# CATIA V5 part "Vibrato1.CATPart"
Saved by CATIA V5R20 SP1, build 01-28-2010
Part number: Vibrato1
Bounding box of the stored display mesh (mm): x -45 to 45, y -32 to 1, z 25 to 40
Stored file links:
  F:\Pro\Emplois\1_Chercheur\ThinkMOTION\MMS\MMS_GR1\abruchon\Catia\Vibrato1.CATPart
  F:\Pro\Emplois\1_Chercheur\ThinkMOTION\MMS\MMS_GR1\abruchon\Catia\Vibrato.CATProduct
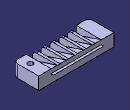
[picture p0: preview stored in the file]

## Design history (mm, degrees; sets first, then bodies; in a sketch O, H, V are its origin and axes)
Set1
  Plane1 to Plane6: linked copy from another document
Body1 (main body)
  Sketch1 on Plane1, origin (0, 0, 0), H (1, 0, 0), V (0, 1, 0)
    line L1 (-45, -2) -> (45, -2)
    line L2 (45, -2) -> (45, -32)
    line L3 (45, -32) -> (-45, -32)
    line L4 (-45, -32) -> (-45, -2)
    reference intersected line E1 through (0, -2) direction (-1, 0) from Plane2
    reference intersected line E2 through (-45, 0) direction (0, 1) from Plane3
    reference intersected line E3 through (45, 0) direction (0, 1) from Plane4
    reference intersected line E4 through (0, -32) direction (-1, 0) from Plane5
    distance L1 E1 = 0
    distance L4 E2 = 0
    distance L2 E3 = 0
    distance L3 E4 = 0
    horizontal: L1 H, L3 H
    vertical: L2 V, L4 V
  Pad1: profile Sketch1, direction (0, 0, 1), up to Plane6
  Sketch2 on face of Pad1 from Sketch1.L2, origin (45, 0, 0), H (0, 1, 0), V (0, 0, 1)
    line L1 (-40, 25) -> (10, 25)
    line L2 (10, 25) -> (10, -15)
    line L3 (10, -15) -> (-40, -15)
    line L4 (-40, -15) -> (-40, 25)
    reference projected line E1 (-32, 40) -> (-2, 40) from edge [face of Pad1 from Sketch1.L2 | end face of Pad1]
    distance E1 L1 = 15
    horizontal: L1 H, L3 H
    vertical: L2 V, L4 V
  Pocket1: profile Sketch2, direction (-1, 0, 0), through (limit type 6)
  Sketch3 on face of Pad1 from Sketch1.L2, origin (45, 0, 0), H (0, 1, 0), V (0, 0, 1)
    line L1 (-9, 35) -> (1, 35)
    point P2 (1, 35)
    line L2 (1, 35) -> (-9, 34)
    line L3 (-9, 34) -> (-9, 35)
    reference projected line E1 (-2, 0) -> (-2, 40) from edge [face of Pad1 from Sketch1.L1 | face of Pad1 from Sketch1.L2]
    reference projected line E2 (-32, 40) -> (-2, 40) from edge [face of Pad1 from Sketch1.L2 | end face of Pad1]
    distance P2 E1 = 3
    distance L1 E2 = 5
    length L3 = 1
    horizontal: L1 H
    vertical: L3 V
  Pad2: profile Sketch3, direction (-1, 0, 0), up to face of Pad1 from Sketch1.L4
  Sketch4 on face of Pad1 from Sketch1.L1, origin (0, -2, 0), H (-1, 0, 0), V (0, 0, 1)
    line L1 (-30, 40) -> (-45, 40)
    line L2 (-45, 40) -> (-45, 25)
    line L3 (-45, 25) -> (-30, 25)
    line L4 (-30, 25) -> (-30, 40)
    reference projected line E1 (-45, 25) -> (45, 25) from edge [face of Pocket1 from Sketch2.L1 | face of Pad1 from Sketch1.L1]
    reference projected line E2 (45, 40) -> (-45, 40) from edge [end face of Pad1 | face of Pad1 from Sketch1.L1]
    reference projected line E3 (-45, 0) -> (-45, 40) from edge [face of Pad1 from Sketch1.L1 | face of Pad1]
    line L5 (30, 40) -> (45, 40)
    line L6 (45, 40) -> (45, 25)
    line L7 (45, 25) -> (30, 25)
    line L8 (30, 25) -> (30, 40)
    reference projected line E4 (45, 0) -> (45, 40) from edge [face of Pad1 | face of Pad1 from Sketch1.L1]
    reference projected line E5 (45, 40) -> (-45, 40) from edge [end face of Pad1 | face of Pad1 from Sketch1.L1]
    reference projected line E6 (-45, 25) -> (45, 25) from edge [face of Pocket1 from Sketch2.L1 | face of Pad1 from Sketch1.L1]
    distance L3 E1 = 0
    distance L1 E2 = 0
    distance E3 L2 = 0
    distance L6 E4 = 0
    distance L5 E5 = 0
    distance L7 E6 = 0
    horizontal: L1 H, L3 H, L5 H, L7 H
    vertical: L2 V, L4 V, L6 V, L8 V
  Pocket2: profile Sketch4, direction (0, 1, 0), through (limit type 6)
  Sketch5 on face of Pad1, origin (45, 0, 0), H (0, 1, 0), V (0, 0, 1)
    line L1 (-32, 40) -> (-32, 40)
    reference projected line E1 (-32, 40) -> (-2, 40) from edge [face of Pad1 from Sketch1.L2 | end face of Pad1]
    line L2 (-32, 30) -> (-2, 40)
    point P3 (-32, 30)
    point P4 (-2, 40)
    line L3 (-2, 40) -> (-32, 40)
    line L4 (-32, 40) -> (-32, 30)
    reference projected line E2 (-32, 40) -> (-2, 40) from edge [face of Pad1 from Sketch1.L2 | end face of Pad1]
    reference projected line E3 (-2, 0) -> (-2, 40) from edge [face of Pocket2 | face of Pad1]
    reference projected line E4 (-32, 0) -> (-32, 40) from edge [face of Pad1 | face of Pad1 from Sketch1.L3]
    reference projected line E5 (-2, 25) -> (-32, 25) from edge [face of Pad1 from Sketch1.L2 | face of Pocket1 from Sketch2.L1]
    distance L1 E1 = 0
    distance L3 E2 = 0
    distance E3 P4 = 0
    distance L4 E4 = 0
    distance P3 E5 = 5
    horizontal: L1 H, L3 H
    vertical: L4 V
  Pocket3: profile Sketch5, direction (-1, 0, 0), through (limit type 6)
  Sketch6 on face of Pad1 from Sketch1.L3, origin (0, -32, 0), H (1, 0, 0), V (0, 0, 1)
    line L1 (30, 40) -> (45, 40)
    line L2 (45, 40) -> (45, 25)
    line L3 (45, 25) -> (30, 25)
    line L4 (30, 25) -> (30, 40)
    reference intersected line E1 through (45, 0) direction (0, 1) from Plane4
    reference projected line E2 (45, 25) -> (-45, 25) from edge [face of Pad1 from Sketch1.L3 | face of Pocket1 from Sketch2.L1]
    reference projected line E3 (45, 40) -> (-45, 40) from edge [face of Pocket2 | face of Pocket3 from Sketch5.L2]
    line L5 (-45, 40) -> (-30, 40)
    line L6 (-30, 40) -> (-30, 25)
    line L7 (-30, 25) -> (-45, 25)
    line L8 (-45, 25) -> (-45, 40)
    reference projected line E4 (45, 40) -> (-45, 40) from edge [face of Pocket2 | face of Pocket3 from Sketch5.L2]
    reference projected line E5 (-45, 40) -> (-45, 30) from edge [face of Pad1 | face of Pocket3 from Sketch5.L2]
    reference projected line E6 (45, 25) -> (-45, 25) from edge [face of Pad1 from Sketch1.L3 | face of Pocket1 from Sketch2.L1]
    line L9 (-22.5, 25) -> (-22.5, 40)
    line L10 (-22.5, 40) -> (-19.5, 40)
    line L11 (-19.5, 40) -> (-19.5, 25)
    point P12 (-19.5, 25)
    line L12 (-19.5, 25) -> (-22.5, 25)
    line L13 (-12, 40) -> (-9, 40)
    line L14 (-9, 40) -> (-9, 25)
    line L15 (-9, 25) -> (-12, 25)
    line L16 (-12, 25) -> (-12, 40)
    line L17 (-1.5, 40) -> (1.5, 40)
    line L18 (1.5, 40) -> (1.5, 25)
    line L19 (1.5, 25) -> (-1.5, 25)
    line L20 (-1.5, 25) -> (-1.5, 40)
    line L21 (9, 40) -> (12, 40)
    line L22 (12, 40) -> (12, 25)
    line L23 (12, 25) -> (9, 25)
    line L24 (9, 25) -> (9, 40)
    line L25 (19.5, 40) -> (22.5, 40)
    line L26 (22.5, 40) -> (22.5, 25)
    line L27 (22.5, 25) -> (19.5, 25)
    line L28 (19.5, 25) -> (19.5, 40)
    distance E1 L2 = 0
    distance L3 E2 = 0
    distance L1 E3 = 0
    distance L5 E4 = 0
    distance L8 E5 = 0
    distance E6 L7 = 0
    length L5 = 15
    distance L9 L6 = 7.5
    length L10 = 3
    length L13 = 3
    distance L16 L6 = 18 (reference)
    length L17 = 3
    distance L20 L6 = 28.5 (reference)
    length L21 = 3
    distance L24 L6 = 39 (reference)
    length L25 = 3
    distance L28 L6 = 49.5 (reference)
    distance L16 L11 = 7.5
    distance L14 L20 = 7.5
    distance L18 L24 = 7.5
    distance L22 L28 = 7.5
    horizontal: L1 H, L3 H, L5 H, L7 H, L10 H, L12 H, L13 H, L15 H, L19 H, L17 H, L23 H, L21 H, L27 H, L25 H
    vertical: L2 V, L4 V, L6 V, L8 V, L9 V, L11 V, L16 V, L14 V, L18 V, L20 V, L22 V, L24 V, L26 V, L28 V
    coincidence: P12 L7
  Pad3: profile Sketch6, direction (0, 1, 0), up to face of Pocket2
  Sketch7 on face of Pad3 from Sketch6.L10, origin (0, 0, 40), H (1, 0, 0), V (0, 1, 0)
    line L1 (-30, -30) -> (-22.5, -30)
    line L2 (-22.5, -30) -> (-22.5, -50)
    line L3 (-22.5, -50) -> (-30, -50)
    line L4 (-30, -50) -> (-30, -30)
    reference projected line E1 (-22.5, -32) -> (-22.5, -2) from edge [face of Pad3 from Sketch6.L10 | face of Pad3 from Sketch6.L9]
    reference projected line E2 (-30, -32) -> (-30, -2) from edge [face of Pad3 from Sketch6.L6 | face of Pad3 from Sketch6.L5]
    line L5 (-12, -30) -> (-12, -50)
    line L6 (-19.5, -50) -> (-19.5, -30)
    line L7 (-19.5, -30) -> (-12, -30)
    line L8 (-12, -50) -> (-19.5, -50)
    line L9 (-1.5, -30) -> (-1.5, -50)
    line L10 (-9, -50) -> (-9, -30)
    line L11 (-9, -30) -> (-1.5, -30)
    line L12 (-1.5, -50) -> (-9, -50)
    line L13 (9, -30) -> (9, -50)
    line L14 (1.5, -50) -> (1.5, -30)
    line L15 (1.5, -30) -> (9, -30)
    line L16 (9, -50) -> (1.5, -50)
    line L17 (19.5, -30) -> (19.5, -50)
    line L18 (12, -50) -> (12, -30)
    line L19 (12, -30) -> (19.5, -30)
    line L20 (19.5, -50) -> (12, -50)
    reference projected line E3 (-19.5, -32) -> (-19.5, -2) from edge [face of Pad3 from Sketch6.L11 | face of Pad3 from Sketch6.L10]
    reference projected line E4 (-9, -32) -> (-9, -2) from edge [face of Pad3 from Sketch6.L14 | face of Pad3 from Sketch6.L13]
    reference projected line E5 (1.5, -32) -> (1.5, -2) from edge [face of Pad3 from Sketch6.L18 | face of Pad3 from Sketch6.L17]
    reference projected line E6 (12, -32) -> (12, -2) from edge [face of Pad3 from Sketch6.L22 | face of Pad3 from Sketch6.L21]
    line L21 (30, -50) -> (22.5, -50)
    line L22 (30, -30) -> (30, -50)
    line L23 (22.5, -50) -> (22.5, -30)
    line L24 (22.5, -30) -> (30, -30)
    reference projected line E7 (22.5, -32) -> (22.5, -2) from edge [face of Pad3 from Sketch6.L26 | face of Pad3 from Sketch6.L25]
    distance L2 E1 = 0
    distance E2 L4 = 0
    distance L5 E1 = 10.5 (reference)
    distance E2 L6 = 10.5 (reference)
    distance L9 E1 = 21 (reference)
    distance E2 L10 = 21 (reference)
    distance L13 E1 = 31.5 (reference)
    distance E2 L14 = 31.5 (reference)
    distance L17 E1 = 42 (reference)
    distance E2 L18 = 42 (reference)
    distance E3 L6 = 0
    distance E4 L10 = 0
    distance E5 L14 = 0
    distance L18 E6 = 0
    distance L23 E6 = 10.5 (reference)
    distance L22 E1 = 52.5 (reference)
    distance E2 L23 = 52.5 (reference)
    distance L23 E7 = 0
    horizontal: L1 H, L3 H, L7 H, L8 H, L12 H, L11 H, L15 H, L16 H, L20 H, L19 H, L21 H, L24 H
    vertical: L2 V, L4 V, L5 V, L6 V, L9 V, L10 V, L13 V, L14 V, L17 V, L18 V, L22 V, L23 V
  Pocket4: profile Sketch7, direction (0, 0, -1), through (limit type 6)
  Fillet1: radius 5, on edge [face of Pocket4 from Sketch7.L24 | face of Pocket3 from Sketch5.L2]
  Fillet2: radius 5, on edge [face of Pocket4 from Sketch7.L19 | face of Pocket3 from Sketch5.L2]
  Fillet3: radius 5, on edge [face of Pocket4 from Sketch7.L15 | face of Pocket3 from Sketch5.L2]
  Fillet4: radius 5, on edge [face of Pocket4 from Sketch7.L11 | face of Pocket3 from Sketch5.L2]
  Fillet5: radius 5, on edge [face of Pocket4 from Sketch7.L7 | face of Pocket3 from Sketch5.L2]
  Fillet6: radius 5, on edge [face of Pocket4 from Sketch7.L1 | face of Pocket3 from Sketch5.L2]
  Fillet7: radius 5, on edge [face of Pad1 | face of Pad1]
  Fillet8: radius 5, on edge [face of Pad1 | face of Pad1]
  Fillet9: radius 5, on edge [face of Pad1 | face of Pad3 from Sketch6.L10]
  Fillet10: radius 5, on edge [face of Pad1 | face of Pad3 from Sketch6.L13]
  Fillet11: radius 5, on edge [face of Pad1 | face of Pad3 from Sketch6.L17]
  Fillet12: radius 5, on edge [face of Pad1 | face of Pad3 from Sketch6.L21]
  Fillet13: radius 5, on edge [face of Pad1 | face of Pad3 from Sketch6.L25]
  Sketch8 on face of Pad3 from Sketch6.L1, origin (0, 0, 40), H (1, 0, 0), V (0, 1, 0)
    circle A1 centre (37, -20) radius 3
    reference projected line E1 (45, -32) -> (45, -2) from edge [face of Pad1 | face of Pad3 from Sketch6.L1]
    reference projected line E2 (30, -2) -> (45, -2) from edge [face of Pad3 from Sketch6.L1 | face of Pocket2]
    radius A1 = 3
    distance A1 E1 = 5
    distance E2 A1 = 15
  Pocket5: profile Sketch8, direction (0, 0, -1), length 10
  Sketch9 on face of Pocket1 from Sketch2.L1, origin (0, 0, 25), H (1, 0, 0), V (0, -1, 0)
    circle A1 centre (-26.25, 29) radius 1.75
    reference projected line E1 (-22.5, 30) -> (-22.5, 32) from edge [face of Pocket1 from Sketch2.L1 | face of Pocket4]
    reference projected line E2 (-30, 30) -> (-30, 32) from edge [face of Pocket4 | face of Pocket1 from Sketch2.L1]
    circle A2 centre (-15.75, 29) radius 1.75
    circle A3 centre (-5.25, 29) radius 1.75
    circle A4 centre (5.25, 29) radius 1.75
    circle A5 centre (15.75, 29) radius 1.75
    circle A6 centre (26.25, 29) radius 1.75
    reference projected line E3 (-19.5, 30) -> (-19.5, 32) from edge [face of Pocket4 | face of Pocket1 from Sketch2.L1]
    reference projected line E4 (-9, 30) -> (-9, 32) from edge [face of Pocket4 | face of Pocket1 from Sketch2.L1]
    reference projected line E5 (1.5, 30) -> (1.5, 32) from edge [face of Pocket4 | face of Pocket1 from Sketch2.L1]
    reference projected line E6 (12, 30) -> (12, 32) from edge [face of Pocket4 | face of Pocket1 from Sketch2.L1]
    reference projected line E7 (22.5, 30) -> (22.5, 32) from edge [face of Pocket4 | face of Pocket1 from Sketch2.L1]
    distance A1 E1 = 2
    distance A1 E2 = 2
    distance A2 E1 = 5 (reference)
    distance A2 E2 = 12.5 (reference)
    distance A3 E1 = 15.5 (reference)
    distance A3 E2 = 23 (reference)
    distance A4 E1 = 26 (reference)
    distance A4 E2 = 33.5 (reference)
    distance A5 E1 = 36.5 (reference)
    distance A5 E2 = 47.5 (reference)
    distance A6 E1 = 47 (reference)
    distance A6 E2 = 58 (reference)
    distance E3 A2 = 2
    distance E4 A3 = 2
    distance E5 A4 = 2
    distance A5 E6 = 2
    distance A6 E7 = 2
  Pocket6: profile Sketch9, direction (0, 0, 1), length 10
